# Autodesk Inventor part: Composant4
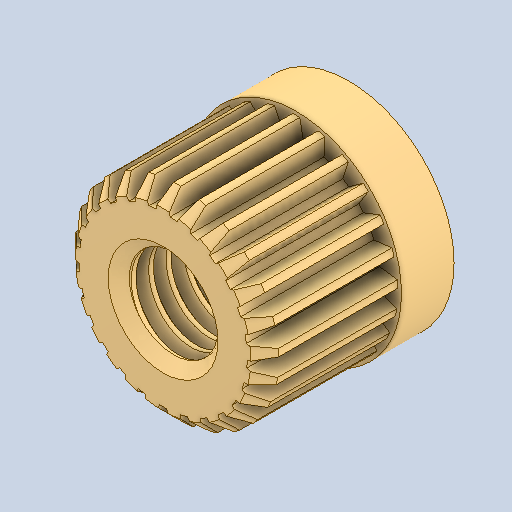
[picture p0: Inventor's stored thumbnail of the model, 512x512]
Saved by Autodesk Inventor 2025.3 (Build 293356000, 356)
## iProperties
Created: 2026-10
Part Number: Composant4
Material: Acier
Document SubType Name: Modeling
Designer: Luis M
Density: 7.85 g/cm^3
Appearance: Valor por defecto
Author: Luis M
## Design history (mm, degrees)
feature "Corps1"
node "Sólido1"
